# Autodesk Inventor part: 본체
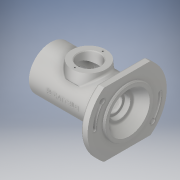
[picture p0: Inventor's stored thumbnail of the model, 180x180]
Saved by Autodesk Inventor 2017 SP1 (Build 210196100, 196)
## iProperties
Part Number: 본체
Material: 알루미늄 6061
Document SubType Name: Modeling
Designer: MRC
Density: 2.7 g/cm^3
Appearance: 알루미늄 - 평지
Mass: 690.309 g
Surface Area: 625.821 cm^2
Volume: 255.67 cm^3
Author: MRC
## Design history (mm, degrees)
sketch "스케치1"
  geometry: C1 r 58 at (0, 0); 1 further point
  constraints: 1 centre point, 1 coincident
  dimensions: "d0" = 116 diameter of C1
extrude "돌출1" new body sketch "스케치1" distance "d1" = 10; taper "d2" = 0 deg
sketch "스케치2"
  geometry: L1 (-33.985, 47)-(33.985, 47); L2 (-33.985, -47)-(33.985, -47); L3 (-58, 0)-(0, 0); A1 r 58 centre (0, 0) between (33.985, 47) and (-33.985, -47) reference; A2 r 58 centre (0, 0) between (33.985, 47) and (-33.985, 47); A3 r 58 centre (0, 0) between (-33.985, -47) and (33.985, -47); 3 further points
  constraints: 8 point on circle, 6 end point, 3 coincident, 2 centre point, 2 horizontal, 2 midpoint, 2 vertical alignment, 1 parallel, 1 other
  dimensions: "d3" = 94 distance between parallel lines of L2 L1
extrude "돌출2" cut sketch "스케치2" distance "d4" = 10; taper "d5" = 0 deg
sketch "스케치3"
  geometry: C1 r 32 at (0, 0); 1 further point
  constraints: 1 centre point, 1 coincident
  dimensions: "d6" = 64 diameter of C1
extrude "돌출3" join sketch "스케치3" distance "d7" = 102; taper "d8" = 0 deg
sketch "스케치6"
  geometry: L1 (-46, 38)-(-46, 20.549); L2 (-46, 20.549)-(-19.473, 20.549); L3 (-19.473, 20.549)-(-21, 38); L4 (-21, 38)-(-46, 38); L5 (0, 32)-(-102, 32) reference; L6 (-19.473, 20.549)-(-19.473, 32); L7 (-102, 32)-(-102, -32) reference; 1 further point
  constraints: 10 end point, 2 vertical, 1 parallel, 1 perpendicular, 1 point on line
  dimensions: "d18" = 38 distance from line of point (0, 0) L4; "d20" = 5 deg angle of L6 L3; "d22" = 56 distance from line of L1.end L7; "d23" = 17.45084 vertical distance of L2.end L3.end; "d123" = 50 diameter of L3.end L1
revolve "회전1" sketch "스케치6" stored, may be unused: angle "d24" = 90 deg
sketch "스케치7"
  geometry: 2 further points
  constraints: 1 coincident
hole "구멍1" sketch "스케치7" at (0, 0) diameter "d25" = 43.376; stored, may be unused: countersink angle "d29" = 90 deg, drill point angle "d31" = 118 deg; dims "d26" = 7, "d27" = 4, "d28" = 2, "d30" = 8
sketch "스케치9"
  geometry: C1 r 36 at (0, 0); 1 further point
  constraints: 1 centre point, 1 coincident
  dimensions: "d32" = 72 diameter of C1
extrude "돌출5" join sketch "스케치9" distance "d33" = 3; taper "d34" = 0 deg
sketch "스케치8"
  geometry: L1 (-102, 0)-(13, 0); L2 (-94, 0)-(-94, 24); L3 (-94, 24)-(-91, 24); L4 (-91, 24)-(-91, 22.5); L5 (-91, 22.5)-(-83, 22.5); L6 (-80, 19.5)-(-80, 18.5); L7 (-79, 17.5)-(-77.75, 17.5); L8 (-77.75, 17.5)-(-77.75, 18.5); L9 (-77.75, 18.5)-(-76, 18.5); L10 (-76, 18.5)-(-76, 17.5); L11 (-76, 17.5)-(-66, 17.5); L12 (-65, 18.5)-(-65, 27); L13 (-65, 27)-(-27, 27); L14 (-27, 27)-(-27, 18.5); L15 (13, -36)-(13, 36) reference; L16 (13, 30)-(13, 0); L17 (-102, -21.688)-(-102, 21.688) reference; L18 (-26, 17.5)-(-16.6, 17.5); L19 (-16, 16.9)-(-16, 15); L20 (-16, 15)-(-14, 15); L21 (-11, 12)-(-11, 11); L22 (-11, 11)-(-8.3, 11); L23 (-8.3, 11)-(-8.3, 14.5); L24 (-7.8, 15)-(-1.7, 15); L25 (-1, 15.404)-(-1, 20); L26 (-1, 20)-(13, 30); L27 (-80, 18.5)-(-79, 17.5); L28 (-65, 18.5)-(-66, 17.5); L29 (-27, 18.5)-(-26, 17.5); L30 (-1.7, 15)-(-1, 15.404); A1 r 3 centre (-83, 19.5) between (-80, 19.5) and (-83, 22.5); A2 r 0.6 centre (-16.6, 16.9) between (-16, 16.9) and (-16.6, 17.5); A3 r 3 centre (-14, 12) between (-11, 12) and (-14, 15); A4 r 0.5 centre (-7.8, 14.5) between (-7.8, 15) and (-8.3, 14.5); 9 further points
  constraints: 56 end point, 18 point on line, 17 perpendicular, 8 point on circle, 8 tangent, 4 centre point, 2 horizontal, 2 midpoint, 1 collinear, 1 horizontal alignment, 1 vertical
  dimensions: "d35" = 3 distance of L2.end L3.end; "d36" = 48 diameter of L3 L1; "d37" = 45 diameter of L5 L1; "d38" = 22 distance between parallel lines of L6 L17; "d39" = 1.75 distance of L8.end L9.end; "d40" = 4 distance between parallel lines of L10 L6; "d41" = 11 distance between parallel lines of L12 L10; "d42" = 37 diameter of L9 L1; "d43" = 35 diameter of L7 L1; "d44" = 54 diameter of L13 L1; "d45" = 38 distance of L12.end L13.end; "d46" = 11 distance of point (-27, 17.5) point (-16, 17.5); "d47" = 14 horizontal distance of L16.start L25.end; "d48" = 5 distance of L19.end point (-11, 15); "d49" = 29 distance between parallel lines of L15 L19 (derived); "d50" = 22 diameter of L22 L1; "d51" = 30 diameter of L20 L1; "d52" = 35 diameter of L18 L1; "d53" = 30 diameter of L24 L1; "d54" = 40 diameter of L25.end L1; "d55" = 60 diameter of L16.start L1; "d56" = 107 distance between parallel lines of L15 L2; "d65" = 3 radius of A1; "d66" = 1 distance of L6.end point (-80, 17.5); "d67" = 1 distance of L7.start point (-80, 17.5) (= d66); "d68" = 1 distance of L12.start point (-65, 17.5); "d69" = 1 distance of L11.end point (-65, 17.5) (= d68); "d70" = 1 distance of L14.end point (-27, 17.5); "d71" = 1 distance of L18.start point (-27, 17.5) (= d70); "d72" = 0.6 radius of A2; "d73" = 3 radius of A3; "d74" = 0.5 radius of A4; "d75" = 7.3 distance between parallel lines of L25 L23; "d76" = 0.7 horizontal distance of L25.start L24.end; "d77" = 30 deg angle of L24 L30
revolve "회전2" sketch "스케치8" stored, may be unused: angle "d58" = 90 deg
sketch "스케치10"
  geometry: C1 r 25 at (0, 0) reference; C2 r 16 at (0, 0); 1 further point
  constraints: 1 centre point, 1 coincident
  dimensions: "d59" = 32 diameter of C2
extrude "돌출6" cut sketch "스케치10" distance "d60" = 30; taper "d61" = 0 deg
chamfer "모따기1" distance "d62" = 1; stored, may be unused: second distance "d63" = 2, angle "d64" = 45 deg
fillet "모깎기1" dims "d78" = 3
sketch "스케치11"
  geometry: L1 (-36.77, -30.854)-(36.77, 30.854); L2 (0, 0)-(0, 48); L3 (-33.985, 47)-(33.985, 47) reference; L4 (0, 0)-(48, 0); A1 r 48 centre (0, 0) between (36.77, 30.854) and (0, 48); 3 further points
  constraints: 6 end point, 4 point on circle, 3 coincident, 1 centre point, 1 horizontal, 1 midpoint, 1 perpendicular
  dimensions: "d80" = 96 diameter of A1; "d81" = 40 deg angle of L4 L1
hole "구멍2" sketch "스케치11" at (36.77, 30.854), (-36.77, -30.854) diameter "d82" = 4.5; stored, may be unused: countersink angle "d86" = 90 deg, drill point angle "d88" = 118 deg; dims "d83" = 7, "d84" = 8, "d85" = 4.4, "d87" = 10
sketch "스케치12"
  geometry: L1 (-48, 0)-(48, 0); L2 (-36.77, -30.854)-(36.77, 30.854); A1 r 48 centre (0, 0) between (48, 0) and (36.77, 30.854); A2 r 48 centre (0, 0) between (48, 0) and (36.77, 30.854); A3 r 52 centre (0, 0) between (52, 0) and (39.834, 33.425); A4 r 44 centre (0, 0) between (44, 0) and (33.706, 28.283); A5 r 4 centre (48, 0) between (44, 0) and (52, 0); A6 r 4 centre (36.77, 30.854) between (39.834, 33.425) and (33.706, 28.283); A7 r 48 centre (0, 0) between (-48, 0) and (-36.77, -30.854); A8 r 52 centre (0, 0) between (-52, 0) and (-39.834, -33.425); A9 r 44 centre (0, 0) between (-44, 0) and (-33.706, -28.283); A10 r 4 centre (-48, 0) between (-44, 0) and (-52, 0); A11 r 4 centre (-36.77, -30.854) between (-39.834, -33.425) and (-33.706, -28.283); 1 further point
  constraints: 24 point on circle, 11 centre point, 8 tangent, 4 end point, 3 concentric, 2 midpoint, 1 coincident, 1 horizontal
  dimensions: "d89" = 96 diameter of A1; "d90" = 40 deg angle of L1 L2; "d91" = 4 radius of A6; "d92" = 4 radius of A11
extrude "돌출7" cut sketch "스케치12" distance "d93" = 4.4; taper "d94" = 0 deg
sketch "스케치13"
  geometry: L1 (-33.985, 47)-(33.985, 47) reference; L2 (48, 0)-(-48, 0); L3 (36.77, -30.854)-(-36.77, 30.854); C1 r 2.25 at (-36.77, 30.854) reference; A1 r 48 centre (0, 0) between (48, 0) and (36.77, -30.854); A2 r 4 centre (-48, 0) between (-52, 0) and (-44, 0) reference; A3 r 48 centre (0, 0) between (-36.77, 30.854) and (-48, 0); A4 r 50.25 centre (0, 0) between (-38.494, 32.3) and (-50.25, 0); A5 r 45.75 centre (0, 0) between (-35.047, 29.408) and (-45.75, 0); A6 r 2.25 centre (-36.77, 30.854) between (-35.047, 29.408) and (-38.494, 32.3); A7 r 2.25 centre (-48, 0) between (-50.25, 0) and (-45.75, 0); A8 r 48 centre (0, 0) between (36.77, -30.854) and (48, 0); A9 r 50.25 centre (0, 0) between (38.494, -32.3) and (50.25, 0); A10 r 45.75 centre (0, 0) between (35.047, -29.408) and (45.75, 0); A11 r 2.25 centre (36.77, -30.854) between (35.047, -29.408) and (38.494, -32.3); A12 r 2.25 centre (48, 0) between (50.25, 0) and (45.75, 0); 1 further point
  constraints: 22 point on circle, 11 centre point, 8 tangent, 4 end point, 2 concentric, 2 midpoint, 1 coincident, 1 horizontal
  dimensions: "d95" = 96 diameter of A1; "d96" = 2.25 radius of A6; "d97" = 2.25 radius of A11
extrude "돌출8" cut sketch "스케치13" distance "d98" = 5.6; taper "d99" = 0 deg
sketch "스케치14"
  geometry: L1 (-48, 0)-(48, 0); L2 (-36.77, -30.854)-(36.77, 30.854); C1 r 4 at (36.77, 30.854); C2 r 4 at (-36.77, -30.854); A1 r 48 centre (0, 0) between (-48, 0) and (-36.77, -30.854); A2 r 2.25 centre (48, 0) between (45.75, 0) and (50.25, 0) reference; A3 r 2.25 centre (36.77, 30.854) between (38.494, 32.3) and (35.047, 29.408) reference; 1 further point
  constraints: 4 end point, 3 centre point, 3 coincident, 2 midpoint, 2 point on circle, 1 horizontal
  dimensions: "d100" = 96 diameter of A1; "d101" = 8 diameter of C1; "d102" = 8 diameter of C2
extrude "돌출9" cut sketch "스케치14" distance "d103" = 10; taper "d104" = 0 deg
fillet "모깎기3" dims "d105" = 3
fillet "모깎기4" dims "d106" = 3
fillet "모깎기5" dims "d107" = 3
chamfer "모따기2" distance "d108" = 1; stored, may be unused: second distance "d109" = 2, angle "d110" = 45 deg
sketch "스케치15"
  geometry: C1 r 25 at (0, 0) reference; A1 r 20.5 centre (0, 0) between (0, 20.5) and (0, -20.5); 1 further point
  constraints: 2 point on circle, 2 vertical alignment, 1 centre point, 1 coincident
  dimensions: "d111" = 41 diameter of A1
hole "구멍3" sketch "스케치15" at (0, 20.5), (0, -20.5) diameter "d112" = 2.459; stored, may be unused: countersink angle "d116" = 90 deg, drill point angle "d118" = 118 deg; dims "d113" = 6, "d114" = 4, "d115" = 2, "d117" = 8
node "작업 평면3"
sketch "스케치16"
  geometry: L1 (10, -46.4)-(10, 46.4) reference; 2 further points
  constraints: 1 horizontal alignment, 1 other
  dimensions: "d120" = 62 distance from line of L1 point (-52, 0)
feature "엠보싱1" sketch "스케치16" dims "d121" = 0.5, "d122" = 0
fillet "모깎기6" dims "d124" = 3
fillet "모깎기7" dims "d125" = 3
node "솔리드1"
other parameters: "d119" = 32
